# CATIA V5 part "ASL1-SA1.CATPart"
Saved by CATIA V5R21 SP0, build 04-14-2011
Part number: ASL1-SA1.SLDPRT
Bounding box of the stored display mesh (mm): x -0.533 to 0.967, y -0.86 to 1.04, z 1.395 to 2.185
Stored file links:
  C:\Users\user\Desktop\CATIA文件\0-最新文件\ASL1-SA1\ASL1-SA1.CATPart
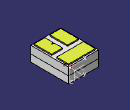
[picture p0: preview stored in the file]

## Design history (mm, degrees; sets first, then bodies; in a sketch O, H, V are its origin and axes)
AxisSystem1: origin (0.2168, 0.3505, 1.395), X (-1, 0, 0), Y (0, 1, 0), Z (0, 0, -1)
Set1
  DatumSurface1 to DatumSurface14
  Line1: stored without definition
  Circle1: stored without definition
  Line2: stored without definition
  Circle2: stored without definition
  Line3: stored without definition
  Circle3: stored without definition
  Line4: stored without definition
  Circle4: stored without definition
  Line5: stored without definition
  Circle5: stored without definition
  Line6: stored without definition
  Circle6: stored without definition
  Line7: stored without definition
  Circle7: stored without definition
  Line8: stored without definition
  Circle8: stored without definition
  Line9 to Line20: stored without definition
  Circle9 to Circle16: stored without definition
  DatumSurface15 to DatumSurface18
  Circle17: stored without definition
  Line21: stored without definition
  Circle18: stored without definition
  Line22: stored without definition
  Circle19: stored without definition
  Circle20: stored without definition
  DatumSurface19 to DatumSurface22
  Circle21: stored without definition
  Line23: stored without definition
  Circle22: stored without definition
  Line24: stored without definition
  Circle23: stored without definition
  Circle24: stored without definition
  DatumSurface23 to DatumSurface26
  Circle25: stored without definition
  Line25: stored without definition
  Circle26: stored without definition
  Line26: stored without definition
  Circle27: stored without definition
  Circle28: stored without definition
  DatumSurface27 to DatumSurface30
  Circle29: stored without definition
  Line27: stored without definition
  Circle30: stored without definition
  Line28: stored without definition
  Circle31: stored without definition
  Circle32: stored without definition
  DatumSurface31 to DatumSurface36
  Line29 to Line40: stored without definition
  DatumSurface37 to DatumSurface42
  Line41 to Line52: stored without definition
  DatumSurface43 to DatumSurface51
  Line53 to Line73: stored without definition
  DatumSurface52 to DatumSurface59
  Line74 to Line91: stored without definition
  DatumSurface60 to DatumSurface67
  Line92 to Line109: stored without definition
  DatumSurface68 to DatumSurface73
  Line110 to Line121: stored without definition
  DatumSurface74 to DatumSurface83
  Line122 to Line145: stored without definition
  Point1 "发光中心（测试原点）": type Between, FirstPoint vertex [face of DatumSurface69], SecondPoint vertex [face of DatumSurface83], Ratio 0.5
  Point2 "几何中心": type Between, FirstPoint vertex [face of DatumSurface75], SecondPoint vertex [face of DatumSurface74], Ratio 0.5
  Point3 "虚拟坐标": (-0.0001, -0.0026, -0.0347), relative to Point1, in AxisSystem1
Body1 (main body)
